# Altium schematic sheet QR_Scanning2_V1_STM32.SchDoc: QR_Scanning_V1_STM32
size 381 x 241 mm; ApprovedBy: VARUN; CheckedBy: VARUN; Author: non; CompanyName: Houston Systom Pvt. Ltd.; DrawnBy: VARUN; Engineer: VARUN; Address1: Greator Noida; SheetNumber: 3; SheetTotal: 3
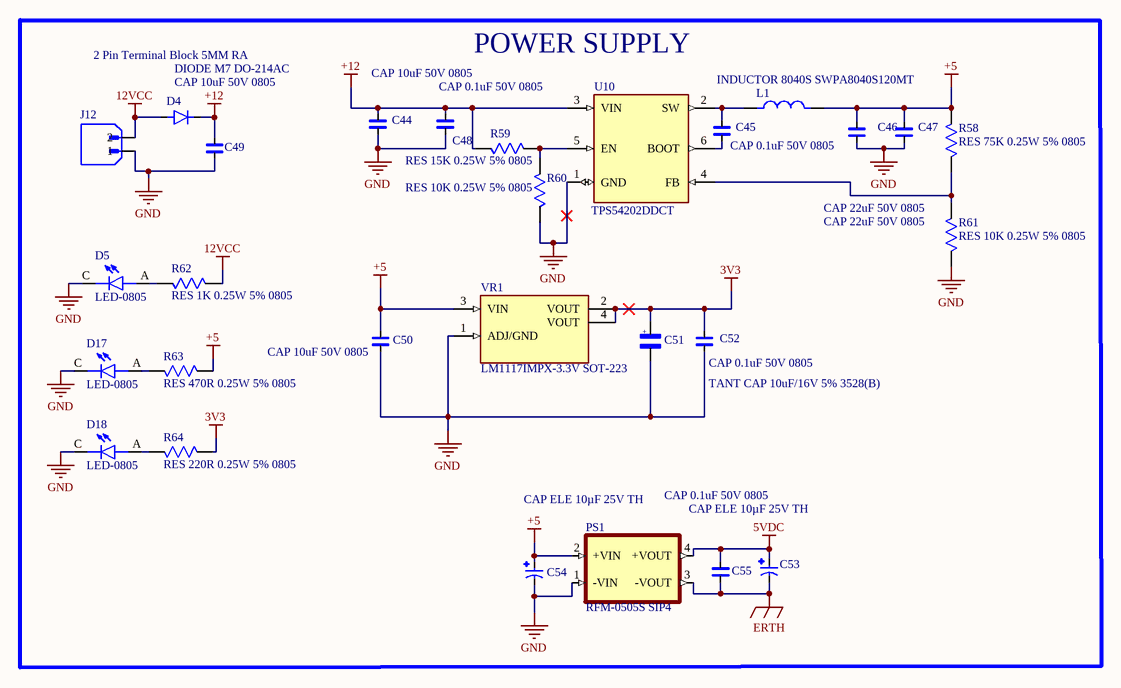
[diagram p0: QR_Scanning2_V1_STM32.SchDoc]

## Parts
C44  CAP 10uF 50V 0805  [CAP CER 0.1uF/50V 5%]
C45  CAP 0.1uF 50V 0805  [CAP CER 0.1uF/50V 5%]
C46  CAP 22uF 50V 0805  [CAP CER 0.1uF/50V 5%]
C47  CAP 22uF 50V 0805  [CAP CER 0.1uF/50V 5%]
C48  CAP 0.1uF 50V 0805  [CAP CER 0.1uF/50V 5%]
C49  CAP 10uF 50V 0805  [CAP CER 0.1uF/50V 5%]
C50  CAP 10uF 50V 0805  [CAP CER 0.1uF/50V 5%]
C51  TANT CAP 10uF/16V 5% 3528(B)  [TANT CAP 3528(B)]
C52  CAP 0.1uF 50V 0805  [CAP CER 0.1uF/50V 5%]
C53  CAP ELE 10µF 25V TH  [CAP ELE 10µF 25V TH]
C54  CAP ELE 10µF 25V TH  [CAP ELE 10µF 25V TH]
C55  CAP 0.1uF 50V 0805  [CAP CER 0.1uF/50V 5%]
D4  DIODE M7 DO-214AC  [DIODE M7 DO-214AC]
D5  LED-0805  [LED-0805]
D17  LED-0805  [LED-0805]
D18  LED-0805  [LED-0805]
J12  2 Pin Terminal Block 5MM RA  [2 Pin Terminal Block 5MM RA]
L1  INDUCTOR 8040S SWPA8040S120MT  [INDUCTOR 8040S SWPA8040S120MT]
PS1  RFM-0505S SIP4  [RFM-0505S]
R58  RES 75K 0.25W 5% 0805  [RES 0805 10K/0.25W 5%]
R59  RES 15K 0.25W 5% 0805  [RES 0805 10K/0.25W 5%]
R60  RES 10K 0.25W 5% 0805  [RES 0805 10K/0.25W 5%]
R61  RES 10K 0.25W 5% 0805  [RES 0805 10K/0.25W 5%]
R62  RES 1K 0.25W 5% 0805  [RES 0805 10K/0.25W 5%]
R63  RES 470R 0.25W 5% 0805  [RES 0805 10K/0.25W 5%]
R64  RES 220R 0.25W 5% 0805  [RES 0805 10K/0.25W 5%]
U10  TPS54202DDCT  [TPS54202DDCT]
VR1  LM1117IMPX-3.3V SOT-223  [LM1117IMPX-3.3V SOT-223]

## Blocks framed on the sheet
POWER SUPPLY: C44-C55 D4 D5 D17 D18 J12 L1 PS1 R58-R64 U10 VR1

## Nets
3V3: C51.1 C52.2 R64.2 VR1.2(VOUT) VR1.4(VOUT)
5VDC: C53.P C55.2 PS1.4(+VOUT)
12VCC: D4.A J12.2 R62.2
+5: C46.2 C47.2 C50.2 C54.P L1.2 PS1.2(+VIN) R58.2 R63.2 VR1.3(VIN)
+12: C44.2 C48.2 C49.2 D4.C(K) R59.1 U10.3(VIN)
ERTH: C53.N C55.1 PS1.3(-VOUT)
GND: C44.1 C46.1 C47.1 C48.1 C49.1 C50.1 C51.2 C52.1 C54.N D5.C D17.C D18.C J12.1 PS1.1(-VIN) R60.1 R61.1 U10.1(GND) VR1.1(ADJ/GND)
NetC45_1: C45.1 U10.6(BOOT)
NetC45_2: C45.2 L1.1 U10.2(SW)
NetD5_A: D5.A R62.1
NetD17_A: D17.A R63.1
NetD18_A: D18.A R64.1
NetR58_1: R58.1 R61.2 U10.4(FB)
NetR59_2: R59.2 R60.2 U10.5(EN)

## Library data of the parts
C44-C50 C52 = CAP CER 0.1uF/50V 5%: CAP CER 0.1uF/50V  Ceramic Capacitor X7R 0805 (2012 Metric) SMT; MF: Samsung; MP: CL21B104KCFNNNE
C51 = TANT CAP 10uF/16V 5% 3528(B): 10 ÂµF Molded Tantalum Polymer Capacitor 25 V 1411 (3528 Metric), 1210 150mOhm TCJB106M025R0150; MF: AVX
C53 C54 = CAP ELE 10µF 25V TH: 10µF 25V Aluminum Electrolytic Capacitors Radial Lead Type TH, Dia-5mm, Pitch-2mm ECEA1EN100UI; MF: Panasonic
C55 = CAP CER 0.1uF/50V 5%: CAP CER 0.1uF/50V  Ceramic Capacitor X7R 0805 (2012 Metric); MF: Samsung; MP: CL21B104KCFNNNE
D4 = DIODE M7 DO-214AC: M7 General Purpose SMD Rectifier Diode SMA (DO-214AC) 1A 1000V 1n4007 RS2MA; MF: Taiwan Semiconductor
D5 D17 D18 = LED-0805: Red 640nm LED Indication - Discrete 1.85V 0805 (2012 Metric) APT2012SRCPRV; MF: Kingbright
J12 = 2 Pin Terminal Block 5MM RA: 2 Pin Terminal Block HDR 5MM THT RA _OQ0271510000G; MF: Amphenol Anytek
L1 = INDUCTOR 8040S SWPA8040S120MT: SWPA8040S120MT SMD 8.0×8.0x4.0mm 8040S 12uH Â±20% 2.8A 142 mOhm SMT Shielded Wirewound Inductor; MF: Abracon LLC; MP: ASPI-8040S-510M-T
PS1 = RFM-0505S: DC-DC Converter/Isolator, SIP4, 1kV unreg, Single Output, 1W, 5V Out, RFM Series ¦ RECOM Power Inc. RFM-0505S
R58-R64 = RES 10K 0.25W 5% 0805: RESISTOR, THICK FILM, 10K, 5%, 0805 0.25W SMT; MP: ERJ-6GEYJ103V; MF: Panasonic Electronic
U10 = TPS54202DDCT: 4.5V to 28V Input, 2A Output, EMI Friendly Synchronous Step-Down Converter SOT23-6; MF: Texas Instruments
VR1 = LM1117IMPX-3.3V SOT-223: LM1117IMPX-3.3V 800-mA 15-V linear voltage regulator SOT-223; MF: Texas Instruments; MP: LM1117IMPX-5.0/NOPB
